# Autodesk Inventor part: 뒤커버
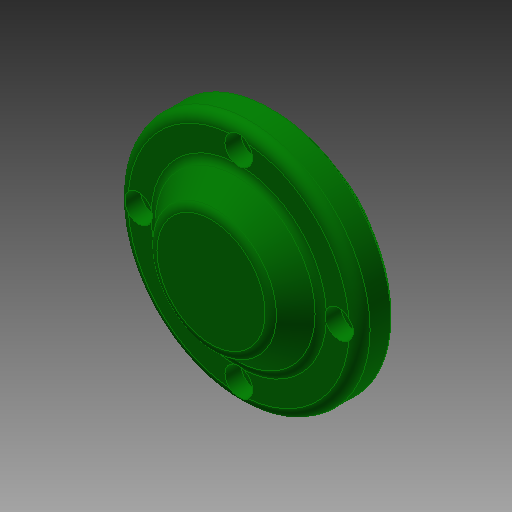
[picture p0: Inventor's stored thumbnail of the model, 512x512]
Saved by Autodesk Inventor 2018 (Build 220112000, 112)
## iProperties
Created: 2017-08
Part Number: 뒤커버
Material: 알루미늄 6061
Document SubType Name: Modeling
Designer: mduedu
Density: 1 g/cm^3
Appearance: 진녹색
Author: mduedu
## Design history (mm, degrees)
sketch "스케치1"
  geometry: C1 r 35 at (0, 0); 1 further point
  constraints: 1 centre point, 1 coincident
  dimensions: "d0" = 70 diameter of C1
extrude "돌출1" new body sketch "스케치1" distance "d1" = 10; taper "d2" = 0 deg
sketch "스케치2"
  geometry: C1 r 24 at (0, 0); 1 further point
  constraints: 1 centre point, 1 coincident
  dimensions: "d3" = 48 diameter of C1
node "작업 평면1"
sketch "스케치3"
  geometry: C1 r 17 at (0, 0); 1 further point
  constraints: 1 centre point, 1 coincident
  dimensions: "d5" = 34 diameter of C1
feature "로프트1" sketch "스케치3" dims "d6" = 0, "d7" = 90 deg, "d8" = 0, "d9" = 90 deg
sketch "스케치4"
  geometry: C1 r 24 at (0, 0) reference; 1 further point
extrude "돌출2" join sketch "스케치4" distance "d10" = 8; taper "d11" = 0 deg
hole "구멍1" diameter "d14" = 40; stored, may be unused: countersink angle "d18" = 90 deg, drill point angle "d20" = 0 deg; dims "d12" = 10, "d13" = 10, "d15" = 6, "d16" = 4, "d17" = 2, "d19" = 12
hole "구멍2" diameter "d23" = 34; stored, may be unused: countersink angle "d27" = 90 deg, drill point angle "d29" = 0 deg; dims "d24" = 6, "d25" = 4, "d26" = 2, "d28" = 6, "d62" = 10, "d63" = 10
chamfer "모따기1" distance "d39" = 1; stored, may be unused: second distance "d40" = 2, angle "d41" = 45 deg
fillet "모깎기1" dims "d42" = 0.3
fillet "모깎기2" dims "d43" = 3
sketch "스케치5" dims "d44" = 58
  geometry: 6 further points
  constraints: 2 vertical alignment, 1 coincident, 7 other
  dimensions: "d47" = 360 deg dimension on point (0, 0) point (0, 29) (derived)
sketch "스케치6"
  geometry: 4 further points
  constraints: 4 other
hole "구멍4" sketch "스케치6" at (0, 29), (-29, 0), (29, 0), (0, -29) diameter "d49" = 4.5; stored, may be unused: countersink angle "d53" = 90 deg, drill point angle "d55" = 0 deg; dims "d50" = 6, "d51" = 8, "d52" = 4.6, "d54" = 8
fillet "모깎기3" dims "d56" = 3
fillet "모깎기4" dims "d57" = 3
fillet "모깎기5" dims "d58" = 3
chamfer "모따기2" distance "d59" = 1; stored, may be unused: second distance "d60" = 2, angle "d61" = 45 deg
node "솔리드1"
other parameters: "d4" = 8
